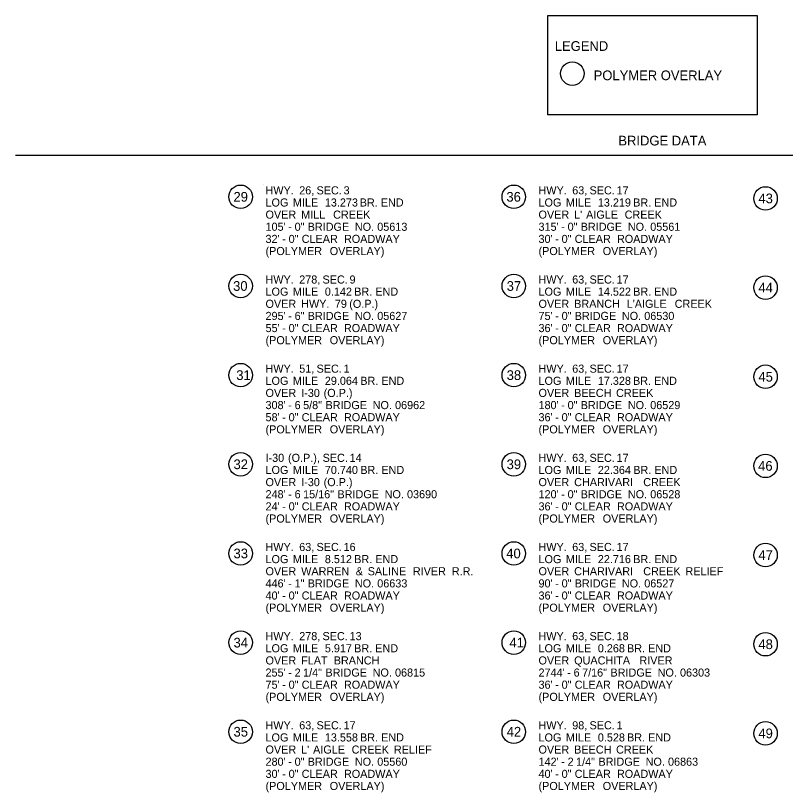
# Model space of a CAD drawing. Extents: x 1930546 to 1934225, y 596452 to 599536.
# Drawn here: x 1932629 to 1933581, y 598576 to 599536 of the extents above; entities that cross this region are included whole.
import ezdxf

# ---------------------------------------------------------------- set-up
doc = ezdxf.new("R2010")
doc.units = 0
doc.layers.add('Default', color=7, linetype='Continuous')
doc.layers.add('R_Border', color=7, linetype='Continuous')

msp = doc.modelspace()

# ---------------------------------------------------------------- linework, layer by layer
at = {"layer": 'R_Border'}
for p, q in [((1934224.56, 599363.54), (1932629.2, 599363.54)), ((1932936.18, 599327.41), (1932936.18, 599327.41))]:
    msp.add_line(p, q, dxfattribs=at)
msp.add_lwpolyline([(1933286.79, 599536.42), (1933545.7, 599536.42), (1933545.7, 599413.76), (1933286.79, 599413.76)], close=True, dxfattribs=at)
for centre in [(1933317.25, 599464.65), (1932907.37, 599312.41), (1933244.93, 599312.41), (1933556.02, 599310.41), (1932907.37, 599202.23), (1933244.93, 599202.23), (1933556.02, 599200.23), (1932907.37, 599092.06), (1933244.93, 599092.06), (1933556.02, 599090.06), (1932907.37, 598981.88), (1933244.93, 598981.88), (1933556.02, 598979.88), (1932907.37, 598871.71), (1933244.93, 598871.71), (1933556.02, 598869.71), (1932907.37, 598761.53), (1933244.93, 598761.53), (1933556.02, 598759.53), (1932907.37, 598651.36), (1933244.93, 598651.36), (1933556.02, 598649.36)]:
    msp.add_circle(centre, 14.52, dxfattribs=at)

# ---------------------------------------------------------------- texts
at = {"layer": 'Default'}
for s, p in [('HWY.', (1932938.13, 599315.41)), (' 26,', (1932976.04, 599315.41)), (' SEC.', (1932997.45, 599315.41)), (' 3', (1933030.86, 599315.41)), ('HWY.', (1933275.48, 599315.41)), (' 63,', (1933313.39, 599315.41)), (' SEC.', (1933334.8, 599315.41)), (' 17', (1933368.21, 599315.41)), ('LOG', (1932938.13, 599300.41)), (' MILE', (1932968.26, 599300.41)), (' 13.273', (1933007.7, 599300.41)), (' BR.', (1933050.79, 599300.41)), (' END', (1933076.82, 599300.41)), ('LOG', (1933275.48, 599300.41)), (' MILE', (1933305.61, 599300.41)), (' 13.219', (1933345.05, 599300.41)), (' BR.', (1933388.74, 599300.41)), (' END', (1933414.77, 599300.41)), ('OVER', (1932938.13, 599285.41)), (' MILL', (1932978.46, 599285.41)), (' CREEK', (1933017.93, 599285.41)), ('OVER', (1933275.48, 599285.41)), (" L'", (1933315.81, 599285.41)), (' AIGLE', (1933330.55, 599285.41)), (' CREEK', (1933378.19, 599285.41)), ("105'", (1932938.13, 599270.41)), (' 0"', (1932970.36, 599270.41)), (' BRIDGE', (1932986.5, 599270.41)), (' NO.', (1933044.81, 599270.41)), (' 05613', (1933072.47, 599270.41)), ("315'", (1933275.48, 599270.41)), (' 0"', (1933307.71, 599270.41)), (' BRIDGE', (1933323.85, 599270.41)), (' NO.', (1933382.16, 599270.41)), (' 05561', (1933409.82, 599270.41)), (' -', (1932962.33, 599270.41)), (' -', (1933299.68, 599270.41)), ("32'", (1932938.13, 599255.41)), (' -', (1932954.95, 599255.41)), (' 0"', (1932962.97, 599255.41)), (' CLEAR', (1932979.11, 599255.41)), (' ROADWAY', (1933031.33, 599255.41)), ("30'", (1933275.48, 599255.41)), (' -', (1933292.3, 599255.41)), (' 0"', (1933300.32, 599255.41)), (' CLEAR', (1933316.46, 599255.41)), (' ROADWAY', (1933368.68, 599255.41)), ('(POLYMER', (1932938.13, 599240.41)), (' OVERLAY)', (1933013.74, 599240.41)), ('(POLYMER', (1933275.48, 599240.41)), (' OVERLAY)', (1933351.09, 599240.41)), ('HWY.', (1932938.13, 599205.23)), (' 278,', (1932976.04, 599205.23)), (' SEC.', (1933004.83, 599205.23)), (' 9', (1933038.24, 599205.23)), ('HWY.', (1933275.48, 599205.23)), (' 63,', (1933313.39, 599205.23)), (' SEC.', (1933334.8, 599205.23)), (' 17', (1933368.21, 599205.23)), ('LOG', (1932938.13, 599190.23)), (' MILE', (1932968.26, 599190.23)), (' 0.142', (1933007.7, 599190.23)), (' BR.', (1933044.02, 599190.23)), (' END', (1933070.05, 599190.23)), ('LOG', (1933275.48, 599190.23)), (' MILE', (1933305.61, 599190.23)), (' 14.522', (1933345.05, 599190.23)), (' BR.', (1933388.76, 599190.23)), (' END', (1933414.79, 599190.23)), ('OVER', (1932938.13, 599175.23)), (' HWY.', (1932978.46, 599175.23)), (' 79', (1933020.06, 599175.23)), (' (O.P.)', (1933037.89, 599175.23)), ('OVER', (1933275.48, 599175.23)), (' BRANCH', (1933315.81, 599175.23)), (" L'AIGLE", (1933380.73, 599175.23)), (' CREEK', (1933440.04, 599175.23)), ("295'", (1932938.13, 599160.23)), (' -', (1932962.33, 599160.23)), (' 6"', (1932970.36, 599160.23)), (' BRIDGE', (1932986.5, 599160.23)), (' NO.', (1933044.81, 599160.23)), (' 05627', (1933072.47, 599160.23)), ("75'", (1933275.48, 599160.23)), (' -', (1933292.3, 599160.23)), (' 0"', (1933300.32, 599160.23)), (' BRIDGE', (1933316.46, 599160.23)), (' NO.', (1933374.77, 599160.23)), (' 06530', (1933402.43, 599160.23)), ("55'", (1932938.13, 599145.23)), (' 0"', (1932962.97, 599145.23)), (' CLEAR', (1932979.11, 599145.23)), (' ROADWAY', (1933031.33, 599145.23)), ("36'", (1933275.48, 599145.23)), (' 0"', (1933300.32, 599145.23)), (' CLEAR', (1933316.46, 599145.23)), (' ROADWAY', (1933368.68, 599145.23)), (' -', (1932954.95, 599145.23)), (' -', (1933292.3, 599145.23)), ('(POLYMER', (1932938.13, 599130.23)), (' OVERLAY)', (1933013.74, 599130.23)), ('(POLYMER', (1933275.48, 599130.23)), (' OVERLAY)', (1933351.09, 599130.23)), ('HWY.', (1932938.13, 599095.06)), (' 51,', (1932976.04, 599095.06)), (' SEC.', (1932997.45, 599095.06)), (' 1', (1933030.86, 599095.06)), ('HWY.', (1933275.48, 599095.06)), (' 63,', (1933313.39, 599095.06)), (' SEC.', (1933334.8, 599095.06)), (' 17', (1933368.21, 599095.06)), ('LOG', (1932938.13, 599080.06)), (' MILE', (1932968.26, 599080.06)), (' 29.064', (1933007.7, 599080.06)), (' BR.', (1933051.51, 599080.06)), (' END', (1933077.54, 599080.06)), ('LOG', (1933275.48, 599080.06)), (' MILE', (1933305.61, 599080.06)), (' 17.328', (1933345.05, 599080.06)), (' BR.', (1933388.53, 599080.06)), (' END', (1933414.56, 599080.06)), ('OVER', (1932938.13, 599065.06)), (' I-30', (1932978.46, 599065.06)), (' (O.P.)', (1933006.24, 599065.06)), ('OVER', (1933275.48, 599065.06)), (' BEECH', (1933315.81, 599065.06)), (' CREEK', (1933367.59, 599065.06)), ("308'", (1932938.13, 599050.06)), (' 6', (1932970.36, 599050.06)), (' 5/8"', (1932980.87, 599050.06)), (' BRIDGE', (1933008.5, 599050.06)), (' NO.', (1933066.81, 599050.06)), (' 06962', (1933094.47, 599050.06)), ("180'", (1933275.48, 599050.06)), (' 0"', (1933307.71, 599050.06)), (' BRIDGE', (1933323.85, 599050.06)), (' NO.', (1933382.16, 599050.06)), (' 06529', (1933409.82, 599050.06)), (' -', (1932962.33, 599050.06)), (' -', (1933299.68, 599050.06)), ("58'", (1932938.13, 599035.06)), (' -', (1932954.95, 599035.06)), (' 0"', (1932962.97, 599035.06)), (' CLEAR', (1932979.11, 599035.06)), (' ROADWAY', (1933031.33, 599035.06)), ("36'", (1933275.48, 599035.06)), (' -', (1933292.3, 599035.06)), (' 0"', (1933300.32, 599035.06)), (' CLEAR', (1933316.46, 599035.06)), (' ROADWAY', (1933368.68, 599035.06)), ('(POLYMER', (1932938.13, 599020.06)), (' OVERLAY)', (1933013.74, 599020.06)), ('(POLYMER', (1933275.48, 599020.06)), (' OVERLAY)', (1933351.09, 599020.06)), ('I-30', (1932938.13, 598984.88)), (' (O.P.),', (1932962.22, 598984.88)), (' SEC.', (1933004.95, 598984.88)), (' 14', (1933038.36, 598984.88)), ('HWY.', (1933275.48, 598984.88)), (' 63,', (1933313.39, 598984.88)), (' SEC.', (1933334.8, 598984.88)), (' 17', (1933368.21, 598984.88)), ('LOG', (1932938.13, 598969.88)), (' MILE', (1932968.26, 598969.88)), (' 70.740', (1933007.7, 598969.88)), (' BR.', (1933051.5, 598969.88)), (' END', (1933077.53, 598969.88)), ('LOG', (1933275.48, 598969.88)), (' MILE', (1933305.61, 598969.88)), (' 22.364', (1933345.05, 598969.88)), (' BR.', (1933388.86, 598969.88)), (' END', (1933414.89, 598969.88)), ('OVER', (1932938.13, 598954.88)), (' I-30', (1932978.46, 598954.88)), (' (O.P.)', (1933006.24, 598954.88)), ('OVER', (1933275.48, 598954.88)), (' CHARIVARI', (1933315.81, 598954.88)), (' CREEK', (1933401.16, 598954.88)), ("248'", (1932938.13, 598939.88)), (' -', (1932962.33, 598939.88)), (' 6', (1932970.36, 598939.88)), (' 15/16"', (1932980.87, 598939.88)), (' BRIDGE', (1933023.28, 598939.88)), (' NO.', (1933081.59, 598939.88)), (' 03690', (1933109.25, 598939.88)), ("120'", (1933275.48, 598939.88)), (' -', (1933299.68, 598939.88)), (' 0"', (1933307.71, 598939.88)), (' BRIDGE', (1933323.85, 598939.88)), (' NO.', (1933382.16, 598939.88)), (' 06528', (1933409.82, 598939.88)), ("24'", (1932938.13, 598924.88)), (' 0"', (1932962.97, 598924.88)), (' CLEAR', (1932979.11, 598924.88)), (' ROADWAY', (1933031.33, 598924.88)), ("36'", (1933275.48, 598924.88)), (' 0"', (1933300.32, 598924.88)), (' CLEAR', (1933316.46, 598924.88)), (' ROADWAY', (1933368.68, 598924.88)), (' -', (1932954.95, 598924.88)), (' -', (1933292.3, 598924.88)), ('(POLYMER', (1932938.13, 598909.88)), (' OVERLAY)', (1933013.74, 598909.88)), ('(POLYMER', (1933275.48, 598909.88)), (' OVERLAY)', (1933351.09, 598909.88)), ('HWY.', (1932938.13, 598874.71)), (' 63,', (1932976.04, 598874.71)), (' SEC.', (1932997.45, 598874.71)), (' 16', (1933030.86, 598874.71)), ('HWY.', (1933275.48, 598874.71)), (' 63,', (1933313.39, 598874.71)), (' SEC.', (1933334.8, 598874.71)), (' 17', (1933368.21, 598874.71)), ('LOG', (1932938.13, 598859.71)), (' MILE', (1932968.26, 598859.71)), (' 8.512', (1933007.7, 598859.71)), (' BR.', (1933044.02, 598859.71)), (' END', (1933070.05, 598859.71)), ('LOG', (1933275.48, 598859.71)), (' MILE', (1933305.61, 598859.71)), (' 22.716', (1933345.05, 598859.71)), (' BR.', (1933388.81, 598859.71)), (' END', (1933414.84, 598859.71)), ('OVER', (1932938.13, 598844.71)), (' WARREN', (1932978.46, 598844.71)), (' &', (1933045.91, 598844.71)), (' SALINE', (1933060.65, 598844.71)), (' RIVER', (1933116.5, 598844.71)), (' R.R.', (1933164.62, 598844.71)), ('OVER', (1933275.48, 598844.71)), (' CHARIVARI', (1933315.81, 598844.71)), (' CREEK', (1933401.16, 598844.71)), (' RELIEF', (1933453.37, 598844.71)), ("446'", (1932938.13, 598829.71)), (' 1"', (1932970.36, 598829.71)), (' BRIDGE', (1932986.5, 598829.71)), (' NO.', (1933044.81, 598829.71)), (' 06633', (1933072.47, 598829.71)), ("90'", (1933275.48, 598829.71)), (' 0"', (1933300.32, 598829.71)), (' BRIDGE', (1933316.46, 598829.71)), (' NO.', (1933374.77, 598829.71)), (' 06527', (1933402.43, 598829.71)), (' -', (1932962.33, 598829.71)), (' -', (1933292.3, 598829.71)), ("40'", (1932938.13, 598814.71)), (' -', (1932954.95, 598814.71)), (' 0"', (1932962.97, 598814.71)), (' CLEAR', (1932979.11, 598814.71)), (' ROADWAY', (1933031.33, 598814.71)), ("36'", (1933275.48, 598814.71)), (' -', (1933292.3, 598814.71)), (' 0"', (1933300.32, 598814.71)), (' CLEAR', (1933316.46, 598814.71)), (' ROADWAY', (1933368.68, 598814.71)), ('(POLYMER', (1932938.13, 598799.71)), (' OVERLAY)', (1933013.74, 598799.71)), ('(POLYMER', (1933275.48, 598799.71)), (' OVERLAY)', (1933351.09, 598799.71)), ('HWY.', (1932938.13, 598764.53)), (' 278,', (1932976.04, 598764.53)), (' SEC.', (1933004.83, 598764.53)), (' 13', (1933038.24, 598764.53)), ('HWY.', (1933275.48, 598764.53)), (' 63,', (1933313.39, 598764.53)), (' SEC.', (1933334.8, 598764.53)), (' 18', (1933368.21, 598764.53)), ('LOG', (1932938.13, 598749.53)), (' MILE', (1932968.26, 598749.53)), (' 5.917', (1933007.7, 598749.53)), (' BR.', (1933043.97, 598749.53)), (' END', (1933070, 598749.53)), ('LOG', (1933275.48, 598749.53)), (' MILE', (1933305.61, 598749.53)), (' 0.268', (1933345.05, 598749.53)), (' BR.', (1933381.14, 598749.53)), (' END', (1933407.17, 598749.53)), ('OVER', (1932938.13, 598734.53)), (' FLAT', (1932978.46, 598734.53)), (' BRANCH', (1933018.68, 598734.53)), ('OVER', (1933275.48, 598734.53)), (' QUACHITA', (1933315.81, 598734.53)), (' RIVER', (1933396.44, 598734.53)), ("255'", (1932938.13, 598719.53)), (' -', (1932962.33, 598719.53)), (' 2', (1932970.36, 598719.53)), (' 1/4"', (1932980.82, 598719.53)), (' BRIDGE', (1933008.45, 598719.53)), (' NO.', (1933066.77, 598719.53)), (' 06815', (1933094.43, 598719.53)), ("2744'", (1933275.48, 598719.53)), (' -', (1933307.07, 598719.53)), (' 6', (1933315.1, 598719.53)), (' 7/16"', (1933325.61, 598719.53)), (' BRIDGE', (1933360.63, 598719.53)), (' NO.', (1933418.94, 598719.53)), (' 06303', (1933446.6, 598719.53)), ("75'", (1932938.13, 598704.53)), (' 0"', (1932962.97, 598704.53)), (' CLEAR', (1932979.11, 598704.53)), (' ROADWAY', (1933031.33, 598704.53)), ("36'", (1933275.48, 598704.53)), (' 0"', (1933300.32, 598704.53)), (' CLEAR', (1933316.46, 598704.53)), (' ROADWAY', (1933368.68, 598704.53)), (' -', (1932954.95, 598704.53)), (' -', (1933292.3, 598704.53)), ('(POLYMER', (1932938.13, 598689.53)), (' OVERLAY)', (1933013.74, 598689.53)), ('(POLYMER', (1933275.48, 598689.53)), (' OVERLAY)', (1933351.09, 598689.53)), ('HWY.', (1932938.13, 598654.36)), (' 63,', (1932976.04, 598654.36)), (' SEC.', (1932997.45, 598654.36)), (' 17', (1933030.86, 598654.36)), ('HWY.', (1933275.48, 598654.36)), (' 98,', (1933313.39, 598654.36)), (' SEC.', (1933334.8, 598654.36)), (' 1', (1933368.21, 598654.36)), ('LOG', (1932938.13, 598639.36)), (' MILE', (1932968.26, 598639.36)), (' 13.558', (1933007.7, 598639.36)), (' BR.', (1933051.18, 598639.36)), (' END', (1933077.21, 598639.36)), ('LOG', (1933275.48, 598639.36)), (' MILE', (1933305.61, 598639.36)), (' 0.528', (1933345.05, 598639.36)), (' BR.', (1933381.14, 598639.36)), (' END', (1933407.17, 598639.36)), ('OVER', (1932938.13, 598624.36)), (" L'", (1932978.46, 598624.36)), (' AIGLE', (1932993.2, 598624.36)), (' CREEK', (1933040.84, 598624.36)), (' RELIEF', (1933093.05, 598624.36)), ('OVER', (1933275.48, 598624.36)), (' BEECH', (1933315.81, 598624.36)), (' CREEK', (1933367.59, 598624.36)), ("280'", (1932938.13, 598609.36)), (' 0"', (1932970.36, 598609.36)), (' BRIDGE', (1932986.5, 598609.36)), (' NO.', (1933044.81, 598609.36)), (' 05560', (1933072.47, 598609.36)), ("142'", (1933275.48, 598609.36)), (' 2', (1933307.71, 598609.36)), (' 1/4"', (1933318.17, 598609.36)), (' BRIDGE', (1933345.8, 598609.36)), (' NO.', (1933404.12, 598609.36)), (' 06863', (1933431.78, 598609.36)), (' -', (1932962.33, 598609.36)), (' -', (1933299.68, 598609.36)), ("30'", (1932938.13, 598594.36)), (' -', (1932954.95, 598594.36)), (' 0"', (1932962.97, 598594.36)), (' CLEAR', (1932979.11, 598594.36)), (' ROADWAY', (1933031.33, 598594.36)), ("40'", (1933275.48, 598594.36)), (' -', (1933292.3, 598594.36)), (' 0"', (1933300.32, 598594.36)), (' CLEAR', (1933316.46, 598594.36)), (' ROADWAY', (1933368.68, 598594.36)), ('(POLYMER', (1932938.13, 598579.36)), (' OVERLAY)', (1933013.74, 598579.36)), ('(POLYMER', (1933275.48, 598579.36)), (' OVERLAY)', (1933351.09, 598579.36))]:
    msp.add_text(s, height=10, rotation=360, dxfattribs=at).set_placement(p)
at = {"layer": 'R_Border'}
for s, p in [('LEGEND', (1933295.6, 599492.74)), ('POLYMER OVERLAY', (1933343.61, 599456.53)), ('BRIDGE DATA', (1933374.15, 599375.86)), ('29', (1932898.53, 599306.41)), ('36', (1933235.81, 599306.41)), ('43', (1933547.23, 599304.41)), ('30', (1932898.06, 599196.23)), ('37', (1933236.15, 599196.23)), ('44', (1933547.23, 599194.23)), ('31', (1932901.98, 599086.06)), ('38', (1933236.15, 599086.06)), ('45', (1933547.23, 599084.06)), ('32', (1932898.58, 598975.88)), ('39', (1933236.1, 598975.88)), ('46', (1933546.9, 598973.88)), ('33', (1932898.58, 598865.71)), ('40', (1933235.63, 598865.71)), ('47', (1933547.23, 598863.71)), ('34', (1932898.58, 598755.53)), ('41', (1933239.55, 598755.53)), ('48', (1933547.23, 598753.53)), ('35', (1932898.58, 598645.36)), ('42', (1933236.15, 598645.36)), ('49', (1933547.19, 598643.36))]:
    msp.add_text(s, height=12, rotation=360, dxfattribs=at).set_placement(p)

doc.saveas('drawing.dxf')
